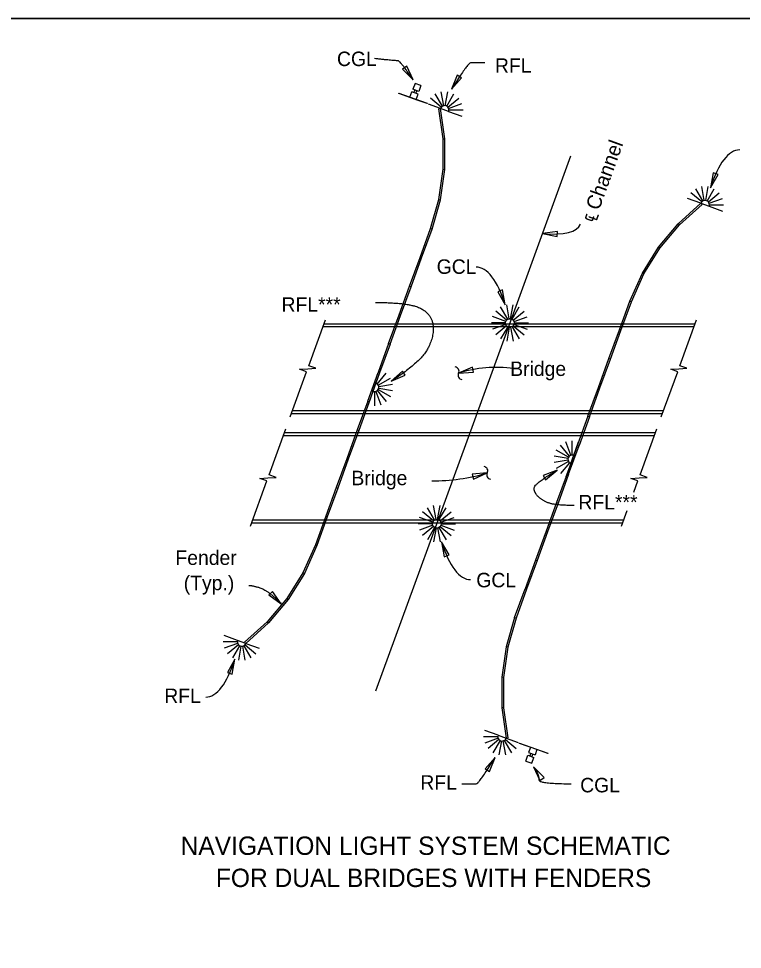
# Model space of a CAD drawing. Extents: x 0 to 1539, y 0 to 973.
# Drawn here: x 378.1 to 756.3, y 486.5 to 973 of the extents above; entities that cross this region are included whole.
import ezdxf

# ---------------------------------------------------------------- set-up
doc = ezdxf.new("R2010")
doc.units = 0
for name, color, linetype in [('Dimension', 7, 'Continuous'), ('Miscellaneous', 7, 'Continuous'), ('Miscellaneous1', 7, 'Continuous'), ('NavLight', 7, 'Continuous'), ('SupstrConc', 7, 'Continuous'), ('TextStructures', 7, 'Continuous'), ('Wood', 7, 'Continuous')]:
    doc.layers.add(name, color=color, linetype=linetype)

msp = doc.modelspace()

# ---------------------------------------------------------------- linework, layer by layer
at = {"layer": 'Dimension'}
for points in [[(0, 0), (1539.4, 0), (1539.4, 972.98), (0, 972.98)], [(584.3, 940.92), (580.94, 948.09), (578.77, 946.59)], [(604.36, 936.04), (609.55, 942.02), (607.29, 943.4)], [(739.66, 884.62), (743.59, 891.5), (741.1, 892.41)], [(651.82, 860.59), (659.6, 859.12), (659.65, 861.76)], [(632.39, 823.38), (630.92, 831.16), (628.44, 830.24)], [(572.83, 783.4), (580.09, 786.58), (578.63, 788.79)], [(607.98, 787.66), (615.88, 788.2), (615.26, 790.77)], [(622.99, 735.5), (615.1, 734.86), (615.75, 732.29)], [(659.59, 736.99), (652.17, 734.2), (653.51, 731.92)], [(599.06, 699.49), (600.54, 691.71), (603.02, 692.63)], [(515.4, 667.13), (510.81, 673.59), (508.94, 671.72)], [(491.13, 638.12), (487.2, 631.24), (489.68, 630.33)], [(627.09, 586.84), (621.91, 580.85), (624.17, 579.48)], [(647.16, 581.95), (650.51, 574.78), (652.69, 576.28)]]:
    msp.add_lwpolyline(points, close=True, dxfattribs=at)
for points in [[(520.02, 764.83), (528.6, 788.39), (524.96, 789.72), (529.18, 789.98), (533.39, 790.24), (529.75, 791.56), (538.5, 815.59)], [(713.91, 764.83), (722.48, 788.39), (718.84, 789.72), (723.06, 789.98), (727.28, 790.24), (723.64, 791.56), (732.38, 815.59)], [(499.25, 707.74), (507.82, 731.31), (504.18, 732.63), (508.4, 732.89), (512.62, 733.16), (508.98, 734.48), (517.72, 758.51)], [(699.61, 725.55), (701.71, 731.31), (698.06, 732.63), (702.28, 732.89), (706.5, 733.16), (702.86, 734.48), (711.61, 758.51)], [(693.13, 707.74), (696.08, 715.85)]]:
    msp.add_lwpolyline(points, dxfattribs=at)
for centre, radius, start, end in [((606.02, 788.69), 2.24, 331.7844, 83.5116), ((627.65, 725.64), 65.06, 81.9279, 107.6051), ((609.96, 786.57), 2.24, 151.7844, 263.5116), ((595.09, 829.03), 97.6, 269.3542, 286.6089), ((621.03, 736.62), 2.24, 330.7882, 82.5154), ((624.93, 734.44), 2.24, 150.7882, 262.5154)]:
    msp.add_arc(centre, radius, start, end, dxfattribs=at)
for centre, major_axis, ratio, start_param, end_param in [((753.99, 847.08), (-0.91, -57.27), 0.343516, 3.141594, 4.002916), ((606.74, 891.61), (-65, 26.05), 0.265294, 2.43766, 3.141592), ((618.06, 785.84), (0.91, -57.27), 0.343516, 2.28027, 3.141592), ((613.4, 737.03), (-0.91, 57.27), 0.343516, 2.28027, 3.141592), ((476.79, 675.66), (0.91, 57.27), 0.343516, 3.141594, 4.002916)]:
    msp.add_ellipse(centre, major_axis=major_axis, ratio=ratio, start_param=start_param, end_param=end_param, dxfattribs=at)
for points in [[(584.3, 940.92), (577.46, 951), (575.11, 950.91), (564.12, 952.05)], [(621.81, 949.82), (616.05, 949.82), (612.74, 949.82), (604.36, 936.04)], [(564.69, 824.61), (581.1, 824.61), (593.25, 819.38), (595.69, 808.32), (588.76, 793.85), (572.83, 783.4)], [(668.48, 718.5), (660.11, 718.5), (652.43, 720.42), (647.11, 725.57), (648.07, 730.28), (659.59, 736.99)], [(498.38, 676.73), (500.4, 676.73), (508.42, 674.11), (515.4, 667.13)], [(609.65, 573.06), (615.41, 573.06), (618.72, 573.06), (627.09, 586.84)], [(647.16, 581.95), (650.3, 577.42), (649.42, 573.06), (666.87, 573.06)]]:
    msp.add_open_spline(points, degree=2, dxfattribs=at)
at = {"layer": 'Miscellaneous'}
for p, q in [((615.73, 761.44), (666.61, 901.24)), ((564.85, 621.64), (615.73, 761.44))]:
    msp.add_line(p, q, dxfattribs=at)
at = {"layer": 'Miscellaneous1'}
msp.add_lwpolyline([(0, 972.98), (1539.4, 972.98), (1539.4, 0), (0, 0)], close=True, dxfattribs=at)
at = {"layer": 'NavLight'}
for p, q in [((585.26, 939.09), (584.16, 936.02)), ((588.35, 937.98), (585.26, 939.09)), ((582.56, 931.98), (583.51, 934.63)), ((586.86, 933.43), (583.51, 934.63)), ((587.25, 934.91), (584.16, 936.02)), ((584.66, 934.22), (585.17, 935.66)), ((585.71, 933.84), (586.23, 935.28)), ((588.35, 937.98), (587.25, 934.91)), ((600.28, 927.46), (598.99, 934.75)), ((601.06, 927.46), (602.34, 934.75)), ((585.91, 930.78), (586.86, 933.43)), ((598.94, 926.69), (593.27, 931.44)), ((599.54, 927.19), (595.84, 933.6)), ((601.79, 927.19), (605.49, 933.6)), ((602.39, 926.69), (608.06, 931.44)), ((598.55, 926.01), (592.38, 928.26)), ((602.78, 924.46), (598.55, 926.01)), ((602.81, 924.44), (609.76, 921.91)), ((602.82, 926.01), (609.77, 928.54)), ((602.95, 925.22), (610.35, 925.22)), ((735.03, 877.15), (729.36, 881.91)), ((735.63, 877.67), (731.93, 884.08)), ((736.4, 877.91), (735.11, 885.2)), ((737.18, 877.91), (738.46, 885.2)), ((737.91, 877.65), (741.61, 884.06)), ((738.51, 877.14), (744.18, 881.9)), ((734.64, 876.46), (727.68, 878.99)), ((734.67, 876.45), (738.9, 874.93)), ((738.9, 876.47), (745.86, 879)), ((739.04, 875.7), (746.44, 875.7)), ((738.9, 874.93), (745.86, 872.4)), ((633.7, 815.84), (630, 822.25)), ((634.43, 816.11), (633.15, 823.4)), ((635.21, 816.11), (636.5, 823.4)), ((635.95, 815.84), (639.65, 822.25)), ((633.1, 815.34), (627.43, 820.1)), ((636.58, 815.35), (642.25, 820.11)), ((632.57, 813.89), (625.17, 813.89)), ((632.71, 814.66), (625.75, 817.2)), ((632.71, 813.13), (625.75, 810.59)), ((633.1, 812.45), (627.43, 807.69)), ((636.58, 812.44), (642.25, 807.68)), ((636.97, 814.66), (643.93, 817.19)), ((636.97, 813.13), (643.93, 810.6)), ((637.1, 813.91), (644.51, 813.91)), ((633.7, 811.95), (630, 805.54)), ((634.43, 811.68), (633.15, 804.39)), ((635.21, 811.68), (636.5, 804.39)), ((635.95, 811.95), (639.65, 805.54)), ((564.82, 782.36), (567.35, 789.32)), ((565.49, 781.97), (570.25, 787.64)), ((565.99, 781.37), (572.41, 785.07)), ((563.26, 778.14), (564.82, 782.36)), ((565.49, 778.52), (570.25, 772.85)), ((565.99, 779.12), (572.41, 775.42)), ((566.26, 780.64), (573.55, 781.92)), ((566.26, 779.86), (573.55, 778.57)), ((563.25, 778.11), (560.72, 771.15)), ((564.03, 777.97), (564.03, 770.56)), ((564.81, 778.1), (567.34, 771.14)), ((665.97, 744.35), (661.21, 750.02)), ((666.64, 744.74), (664.11, 751.7)), ((667.41, 744.88), (667.41, 752.28)), ((668.18, 744.74), (670.71, 751.7)), ((665.46, 743.75), (659.05, 747.45)), ((666.66, 740.51), (668.18, 744.74)), ((665.2, 743.02), (657.91, 744.3)), ((665.2, 742.23), (657.91, 740.95)), ((665.44, 741.47), (659.03, 737.77)), ((665.96, 740.87), (661.2, 735.2)), ((666.65, 740.48), (664.11, 733.52)), ((594.91, 710.42), (589.24, 715.18)), ((595.51, 710.93), (591.81, 717.34)), ((596.25, 711.19), (594.96, 718.48)), ((597.03, 711.19), (598.31, 718.48)), ((597.76, 710.93), (601.46, 717.34)), ((598.39, 710.43), (604.06, 715.19)), ((594.52, 709.75), (587.57, 712.28)), ((598.79, 709.74), (605.74, 712.28)), ((594.39, 708.98), (586.98, 708.98)), ((594.52, 708.21), (587.57, 705.68)), ((594.91, 707.53), (589.24, 702.77)), ((595.51, 707.03), (591.81, 700.62)), ((596.25, 706.76), (594.96, 699.47)), ((597.03, 706.76), (598.31, 699.47)), ((597.76, 707.03), (601.46, 700.62)), ((598.39, 707.52), (604.06, 702.76)), ((598.79, 708.21), (605.74, 705.68)), ((598.92, 708.99), (606.32, 708.99)), ((492.42, 647.18), (485.02, 647.18)), ((492.56, 647.95), (485.6, 650.48)), ((496.79, 646.42), (492.56, 647.95)), ((492.56, 646.41), (485.6, 643.87)), ((492.95, 645.73), (487.28, 640.97)), ((493.55, 645.23), (489.85, 638.82)), ((494.28, 644.96), (493, 637.67)), ((495.06, 644.96), (496.35, 637.67)), ((495.83, 645.21), (499.53, 638.8)), ((496.43, 645.72), (502.1, 640.96)), ((496.82, 646.41), (503.78, 643.88)), ((628.65, 598.43), (621.69, 600.96)), ((628.68, 598.42), (632.9, 596.86)), ((628.51, 597.65), (621.11, 597.65)), ((628.64, 596.87), (621.68, 594.34)), ((629.07, 596.19), (623.4, 591.43)), ((629.66, 595.68), (625.96, 589.27)), ((630.4, 595.42), (629.11, 588.13)), ((631.18, 595.42), (632.47, 588.13)), ((631.91, 595.68), (635.62, 589.27)), ((632.51, 596.19), (638.18, 591.43)), ((632.9, 596.86), (639.08, 594.62)), ((645.55, 592.09), (644.6, 589.45)), ((644.6, 589.45), (647.95, 588.24)), ((645.74, 589.04), (645.23, 587.6)), ((646.8, 588.66), (646.29, 587.22)), ((648.9, 590.89), (647.95, 588.24)), ((643.11, 584.89), (644.21, 587.96)), ((643.11, 584.89), (646.2, 583.79)), ((644.21, 587.96), (647.3, 586.85)), ((646.2, 583.79), (647.3, 586.85))]:
    msp.add_line(p, q, dxfattribs=at)
for centre in [(634.82, 813.89), (596.64, 708.98)]:
    msp.add_circle(centre, 2.25, dxfattribs=at)
for centre, start, end in [((600.67, 925.24), 339.6086, 160), ((736.79, 875.7), 340, 160.3914), ((564.05, 780.25), 249.6086, 70), ((667.41, 742.63), 70, 250.3914), ((494.67, 647.18), 160, 340.3914), ((630.79, 597.63), 159.6086, 340)]:
    msp.add_arc(centre, 2.25, start, end, dxfattribs=at)
at = {"layer": 'SupstrConc'}
for p, q in [((537.74, 813.52), (731.63, 813.52)), ((537.18, 811.98), (731.07, 811.98)), ((714.49, 766.44), (520.61, 766.44)), ((715.05, 767.98), (521.17, 767.98)), ((710.29, 754.89), (516.41, 754.89)), ((710.85, 756.44), (516.97, 756.44)), ((694.28, 710.89), (500.39, 710.89)), ((693.71, 709.35), (499.83, 709.35))]:
    msp.add_line(p, q, dxfattribs=at)
at = {"layer": 'Wood'}
for p, q in [((598.55, 926.01), (597.73, 925.89)), ((599.95, 910.11), (597.73, 925.89)), ((600.78, 910.17), (598.55, 926.01)), ((599.95, 910.11), (600.78, 910.17)), ((599.95, 894.22), (599.95, 910.11)), ((600.78, 894.17), (600.78, 910.17)), ((597.74, 878.49), (599.95, 894.22)), ((598.55, 878.32), (600.78, 894.17)), ((599.95, 894.22), (600.78, 894.17)), ((593.35, 863.2), (597.74, 878.49)), ((594.14, 862.94), (598.55, 878.32)), ((597.74, 878.49), (598.55, 878.32)), ((722.78, 865.76), (734.67, 876.47)), ((723.38, 865.18), (735.23, 875.85)), ((734.67, 876.47), (735.23, 875.85)), ((587.89, 848.19), (593.35, 863.2)), ((588.67, 847.91), (594.14, 862.94)), ((593.35, 863.2), (594.14, 862.94)), ((712.5, 853.5), (722.78, 865.76)), ((713.17, 853.01), (723.38, 865.18)), ((723.38, 865.18), (722.78, 865.76)), ((704.02, 839.94), (712.5, 853.5)), ((704.76, 839.54), (713.17, 853.01)), ((713.17, 853.01), (712.5, 853.5)), ((582.42, 833.16), (587.89, 848.19)), ((583.2, 832.87), (588.67, 847.91)), ((588.67, 847.91), (587.89, 848.19)), ((697.51, 825.32), (704.02, 839.94)), ((698.28, 825.01), (704.76, 839.54)), ((704.76, 839.54), (704.02, 839.94)), ((576.94, 818.12), (582.42, 833.16)), ((577.73, 817.84), (583.2, 832.87)), ((583.2, 832.87), (582.42, 833.16)), ((692.04, 810.28), (697.51, 825.32)), ((692.82, 810), (698.28, 825.01)), ((698.28, 825.01), (697.51, 825.32)), ((571.47, 803.09), (576.94, 818.12)), ((572.25, 802.8), (577.73, 817.84)), ((577.73, 817.84), (576.94, 818.12)), ((686.57, 795.25), (692.04, 810.28)), ((687.35, 794.96), (692.82, 810)), ((692.04, 810.28), (692.82, 810)), ((571.47, 803.09), (566, 788.05)), ((572.25, 802.8), (566.78, 787.77)), ((572.25, 802.8), (571.47, 803.09)), ((681.09, 780.21), (686.57, 795.25)), ((681.88, 779.93), (687.35, 794.96)), ((686.57, 795.25), (687.35, 794.96)), ((560.53, 773.02), (566, 788.05)), ((560.53, 773.02), (566, 788.05)), ((566.78, 787.77), (561.31, 772.73)), ((566.78, 787.77), (561.31, 772.73)), ((566.78, 787.77), (566, 788.05)), ((566.78, 787.77), (566, 788.05)), ((675.62, 765.18), (681.09, 780.21)), ((676.4, 764.89), (681.88, 779.93)), ((681.09, 780.21), (681.88, 779.93)), ((560.53, 773.02), (555.05, 757.98)), ((561.31, 772.73), (555.84, 757.7)), ((561.31, 772.73), (560.53, 773.02)), ((675.62, 765.18), (670.15, 750.14)), ((676.4, 764.89), (670.93, 749.86)), ((675.62, 765.18), (676.4, 764.89)), ((555.05, 757.98), (549.59, 742.97)), ((555.84, 757.7), (550.37, 742.66)), ((555.84, 757.7), (555.05, 757.98)), ((670.15, 750.14), (664.68, 735.11)), ((665.46, 734.82), (670.93, 749.86)), ((670.15, 750.14), (670.93, 749.86)), ((549.58, 742.94), (544.12, 727.94)), ((550.37, 742.66), (544.89, 727.62)), ((550.37, 742.66), (549.58, 742.94)), ((664.68, 735.11), (659.2, 720.07)), ((665.46, 734.82), (659.99, 719.79)), ((664.68, 735.11), (665.46, 734.82)), ((544.11, 727.91), (538.64, 712.87)), ((544.89, 727.62), (539.42, 712.59)), ((544.89, 727.62), (544.11, 727.91)), ((659.2, 720.07), (653.73, 705.04)), ((659.2, 720.07), (659.99, 719.79)), ((659.99, 719.79), (654.52, 704.78)), ((538.64, 712.87), (533.17, 697.87)), ((539.42, 712.59), (533.95, 697.55)), ((539.42, 712.59), (538.64, 712.87)), ((653.73, 705.04), (648.26, 690)), ((654.51, 704.75), (649.05, 689.74)), ((653.73, 705.04), (654.51, 704.75)), ((533.17, 697.87), (526.7, 683.33)), ((533.95, 697.55), (527.44, 682.94)), ((533.17, 697.87), (533.95, 697.55)), ((648.26, 690), (642.79, 674.97)), ((649.04, 689.72), (643.57, 674.68)), ((648.26, 690), (649.04, 689.72)), ((526.7, 683.33), (518.29, 669.86)), ((527.44, 682.94), (518.96, 669.37)), ((526.7, 683.33), (527.44, 682.94)), ((637.31, 659.93), (642.79, 674.97)), ((643.57, 674.68), (638.11, 659.67)), ((642.79, 674.97), (643.57, 674.68)), ((518.29, 669.86), (508.08, 657.69)), ((518.96, 669.37), (508.68, 657.11)), ((518.29, 669.86), (518.96, 669.37)), ((508.08, 657.69), (496.23, 647.03)), ((508.68, 657.11), (496.79, 646.41)), ((508.08, 657.69), (508.68, 657.11)), ((637.31, 659.93), (632.9, 644.55)), ((638.11, 659.67), (633.72, 644.38)), ((638.11, 659.67), (637.31, 659.93)), ((496.79, 646.41), (496.23, 647.03)), ((632.9, 644.55), (630.68, 628.71)), ((633.72, 644.38), (631.51, 628.65)), ((633.72, 644.38), (632.9, 644.55)), ((630.68, 628.71), (630.68, 612.71)), ((631.51, 628.65), (630.68, 628.71)), ((631.51, 628.65), (631.51, 612.77)), ((631.51, 612.77), (630.68, 612.71)), ((630.68, 612.71), (632.9, 596.86)), ((631.51, 612.77), (633.73, 596.98)), ((632.9, 596.86), (633.73, 596.98))]:
    msp.add_line(p, q, dxfattribs=at)
for points in [[(586.29, 930.44), (576.76, 933.86), (576.82, 934.04), (582.12, 932.14)], [(582.12, 932.14), (591.65, 928.72), (591.58, 928.55), (586.29, 930.44)], [(649.34, 590.73), (639.81, 594.15), (639.87, 594.33), (645.17, 592.43)], [(645.17, 592.43), (654.7, 589.01), (654.64, 588.83), (649.34, 590.73)]]:
    msp.add_lwpolyline(points, dxfattribs=at)

# ---------------------------------------------------------------- texts
at = {"layer": 'Dimension'}
for s, height, p in [('Fender', 7.56, (460.07, 687.43)), ('(Typ.)', 7.56, (464.41, 674.23)), ('NAVIGATION LIGHT SYSTEM SCHEMATIC', 9.6, (462.76, 535.88)), ('FOR DUAL BRIDGES WITH FENDERS', 9.6, (481.19, 519.08))]:
    msp.add_text(s, height=height, dxfattribs=at).set_placement(p)
at = {"layer": 'TextStructures'}
for s, p in [('CGL', (544.49, 948.17)), ('RFL', (627.01, 944.68)), ('GCL', (596.57, 839.58)), ('RFL***', (515.51, 819.76)), ('Bridge ', (634.98, 786.2)), ('Bridge ', (552.03, 729.11)), ('RFL***', (670.62, 716.44)), ('GCL', (617.27, 675.74)), ('RFL', (454.24, 615.25)), ('RFL', (588.03, 569.94)), ('CGL', (671.54, 568.57))]:
    msp.add_text(s, height=7.56, dxfattribs=at).set_placement(p)
msp.add_text('℄ Channel', height=7.56, rotation=70, dxfattribs=at).set_placement((678.97, 865.84))

doc.saveas('drawing.dxf')
